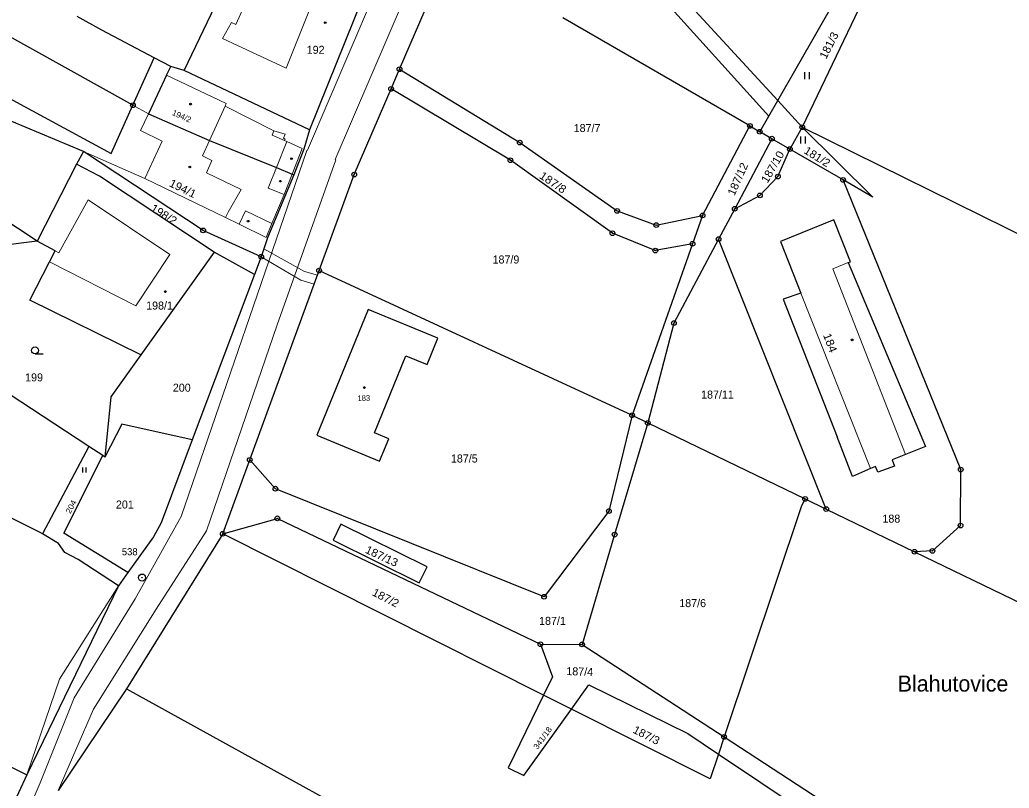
# Model space of a CAD drawing. Extents: x -504006 to -501322, y -1128098 to -1124665.
# Drawn here: x -502549.5 to -502339.3, y -1126824.4 to -1126661.3 of the extents above; entities that cross this region are included whole.
import ezdxf
from ezdxf.enums import TextEntityAlignment as Align

# ---------------------------------------------------------------- set-up
doc = ezdxf.new("R2010")
doc.units = 0
doc.header["$LTSCALE"] = 0.68
for name, color, linetype, lineweight in [('1', 7, 'Continuous', 25), ('13', 7, 'Continuous', 13), ('3', 7, 'Continuous', 25), ('4', 7, 'Continuous', 13), ('5', 7, 'Continuous', 25), ('7', 7, 'Continuous', 13), ('8', 7, 'Continuous', 25)]:
    doc.layers.add(name, color=color, linetype=linetype, lineweight=lineweight)
doc.layers.add('2', color=7, linetype='Continuous')

msp = doc.modelspace()

# ---------------------------------------------------------------- linework, layer by layer
at = {"layer": '1'}
for p, q in [((-502514.61, -1126672.05), (-502498.34, -1126637.96)), ((-502388.53, -1126678.42), (-502367.75, -1126642.18)), ((-502468.87, -1126671.79), (-502458.21, -1126646.98)), ((-502473.55, -1126648.9), (-502487.98, -1126684.63)), ((-502532.13, -1126663.52), (-502537.38, -1126660.61)), ((-502525.52, -1126679.45), (-502556.87, -1126662.01)), ((-502394.44, -1126683.84), (-502434.16, -1126660.88)), ((-502520.99, -1126669.37), (-502532.13, -1126663.52)), ((-502525.52, -1126679.45), (-502520.99, -1126669.37)), ((-502517.46, -1126671.21), (-502520.99, -1126669.37)), ((-502518.34, -1126673.06), (-502522.22, -1126681.29)), ((-502518.34, -1126673.06), (-502517.46, -1126671.21)), ((-502514.61, -1126672.05), (-502517.46, -1126671.21)), ((-502487.98, -1126684.63), (-502514.61, -1126672.05)), ((-502470.66, -1126675.96), (-502468.87, -1126671.79)), ((-502468.87, -1126671.79), (-502443.33, -1126687.38)), ((-502535.97, -1126689.29), (-502570.56, -1126674.86)), ((-502552.7, -1126677.43), (-502530.11, -1126689.67)), ((-502445.31, -1126691.13), (-502470.66, -1126675.96)), ((-502530.11, -1126689.67), (-502525.52, -1126679.45)), ((-502390.44, -1126681.76), (-502388.53, -1126678.42)), ((-502522.22, -1126681.29), (-502509.26, -1126686.91)), ((-502392.34, -1126685.06), (-502390.44, -1126681.76)), ((-502487.98, -1126684.63), (-502489.17, -1126688.78)), ((-502404.48, -1126702.82), (-502394.44, -1126683.84)), ((-502394.44, -1126683.84), (-502392.34, -1126685.06)), ((-502389.77, -1126686.54), (-502392.34, -1126685.06)), ((-502383.3, -1126684.1), (-502243.09, -1126753.39)), ((-502383.3, -1126684.1), (-502368.31, -1126698.95)), ((-502509.26, -1126686.91), (-502495.03, -1126692.69)), ((-502443.33, -1126687.38), (-502422.64, -1126701.87)), ((-502389.77, -1126686.54), (-502397.66, -1126701.4)), ((-502385.94, -1126688.76), (-502389.77, -1126686.54)), ((-502535.97, -1126689.29), (-502537.47, -1126691.97)), ((-502510.58, -1126706), (-502535.97, -1126689.29)), ((-502489.17, -1126688.78), (-502491.34, -1126694.18)), ((-502374.62, -1126695.3), (-502385.94, -1126688.76)), ((-502537.47, -1126691.97), (-502545.88, -1126708.26)), ((-502532.6, -1126694.5), (-502537.47, -1126691.97)), ((-502423.63, -1126706.61), (-502445.31, -1126691.13)), ((-502491.34, -1126694.18), (-502496.89, -1126707.57)), ((-502495.03, -1126692.69), (-502491.67, -1126694.05)), ((-502491.67, -1126694.05), (-502491.34, -1126694.18)), ((-502545.88, -1126708.26), (-502566.86, -1126694.62)), ((-502508.21, -1126710.63), (-502532.6, -1126694.5)), ((-502368.31, -1126698.95), (-502374.62, -1126695.3)), ((-502349.64, -1126756.78), (-502374.62, -1126695.3)), ((-502397.66, -1126701.4), (-502392.31, -1126698.58)), ((-502422.64, -1126701.87), (-502414.31, -1126704.87)), ((-502397.66, -1126701.4), (-502401.08, -1126707.84)), ((-502414.31, -1126704.87), (-502404.48, -1126702.82)), ((-502404.48, -1126702.82), (-502406.61, -1126708.85)), ((-502376.58, -1126703.79), (-502387.96, -1126708.39)), ((-502373.05, -1126712.67), (-502376.58, -1126703.79)), ((-502498.25, -1126711.6), (-502510.58, -1126706)), ((-502414.52, -1126710.3), (-502423.63, -1126706.61)), ((-502545.88, -1126708.26), (-502584.04, -1126713.35)), ((-502542, -1126710.33), (-502545.88, -1126708.26)), ((-502496.89, -1126707.57), (-502498.25, -1126711.6)), ((-502406.61, -1126708.85), (-502419.46, -1126745.24)), ((-502406.61, -1126708.85), (-502414.52, -1126710.3)), ((-502401.08, -1126707.84), (-502410.56, -1126725.68)), ((-502378.21, -1126765.17), (-502401.08, -1126707.84)), ((-502387.96, -1126708.39), (-502383.61, -1126719.33)), ((-502543.2, -1126712.66), (-502542, -1126710.33)), ((-502508.21, -1126710.63), (-502523.8, -1126732.39)), ((-502499.66, -1126715.34), (-502508.21, -1126710.63)), ((-502547.39, -1126720.79), (-502543.2, -1126712.66)), ((-502498.25, -1126711.6), (-502499.66, -1126715.34)), ((-502373.53, -1126712.85), (-502373.05, -1126712.67)), ((-502373.53, -1126712.85), (-502357.15, -1126751.91)), ((-502534.85, -1126751.89), (-502591.17, -1126714.91)), ((-502500.68, -1126754.74), (-502485.95, -1126714.53)), ((-502485.95, -1126714.53), (-502419.46, -1126745.24)), ((-502499.66, -1126715.34), (-502512.9, -1126750.49)), ((-502383.61, -1126719.33), (-502387.33, -1126720.64)), ((-502523.8, -1126732.39), (-502547.39, -1126720.79)), ((-502387.33, -1126720.64), (-502375.92, -1126749.84)), ((-502475.56, -1126722.78), (-502486.4, -1126749.48)), ((-502460.7, -1126728.86), (-502475.56, -1126722.78)), ((-502410.56, -1126725.68), (-502416.13, -1126746.87)), ((-502463.01, -1126734.5), (-502460.7, -1126728.86)), ((-502523.8, -1126732.39), (-502530.23, -1126741.35)), ((-502474.21, -1126749.01), (-502467.52, -1126732.66)), ((-502467.52, -1126732.66), (-502463.01, -1126734.5)), ((-502530.23, -1126741.35), (-502531.47, -1126754.11)), ((-502419.46, -1126745.24), (-502424.37, -1126765.58)), ((-502419.46, -1126745.24), (-502416.13, -1126746.87)), ((-502527.85, -1126747.13), (-502531.47, -1126754.11)), ((-502512.9, -1126750.49), (-502527.85, -1126747.13)), ((-502416.13, -1126746.87), (-502423.16, -1126770.59)), ((-502416.13, -1126746.87), (-502382.7, -1126763)), ((-502512.9, -1126750.49), (-502519.53, -1126768.1)), ((-502486.4, -1126749.48), (-502473.12, -1126755.02)), ((-502471.16, -1126750.26), (-502474.21, -1126749.01)), ((-502473.12, -1126755.02), (-502471.16, -1126750.26)), ((-502372.64, -1126758.22), (-502375.92, -1126749.84)), ((-502534.85, -1126751.89), (-502544.71, -1126770.39)), ((-502531.93, -1126753.81), (-502534.85, -1126751.89)), ((-502357.15, -1126751.91), (-502361.39, -1126753.6)), ((-502540.17, -1126770.24), (-502531.93, -1126753.81)), ((-502531.47, -1126754.11), (-502531.93, -1126753.81)), ((-502506.41, -1126770.39), (-502500.68, -1126754.74)), ((-502495.24, -1126760.83), (-502500.68, -1126754.74)), ((-502361.39, -1126753.6), (-502364.23, -1126754.73)), ((-502364.23, -1126754.73), (-502363.71, -1126756.02)), ((-502368.83, -1126756.55), (-502372.64, -1126758.22)), ((-502367.74, -1126756.12), (-502368.83, -1126756.55)), ((-502367.27, -1126757.31), (-502367.74, -1126756.12)), ((-502363.71, -1126756.02), (-502367.27, -1126757.31)), ((-502349.67, -1126768.66), (-502349.64, -1126756.78)), ((-502438.14, -1126783.76), (-502495.24, -1126760.83)), ((-502545.19, -1126770.1), (-502560.46, -1126762.54)), ((-502382.7, -1126763), (-502383.45, -1126764.45)), ((-502382.7, -1126763), (-502378.21, -1126765.17)), ((-502424.37, -1126765.58), (-502438.14, -1126783.76)), ((-502383.45, -1126764.45), (-502399.9, -1126813.53)), ((-502378.21, -1126765.17), (-502359.46, -1126774.22)), ((-502519.53, -1126768.1), (-502521.15, -1126771.02)), ((-502349.67, -1126768.66), (-502355.65, -1126774.03)), ((-502544.71, -1126770.39), (-502545.19, -1126770.1)), ((-502541.29, -1126772.48), (-502544.71, -1126770.39)), ((-502526.56, -1126778.62), (-502540.17, -1126770.24)), ((-502506.41, -1126770.39), (-502526.88, -1126803.35)), ((-502521.15, -1126771.02), (-502526.56, -1126778.62)), ((-502438.25, -1126804.65), (-502506.41, -1126770.39)), ((-502423.16, -1126770.59), (-502430.09, -1126793.88)), ((-502539.95, -1126774.41), (-502541.29, -1126772.48)), ((-502355.65, -1126774.03), (-502359.46, -1126774.22)), ((-502537.13, -1126775.85), (-502539.95, -1126774.41)), ((-502528.59, -1126781.47), (-502537.13, -1126775.85)), ((-502359.46, -1126774.22), (-502305.89, -1126800.07)), ((-502526.56, -1126778.62), (-502528.59, -1126781.47)), ((-502528.59, -1126781.47), (-502548.07, -1126821.6)), ((-502438.93, -1126793.84), (-502436.36, -1126800.79)), ((-502438.93, -1126793.84), (-502430.09, -1126793.88)), ((-502430.09, -1126793.88), (-502399.9, -1126813.53)), ((-502436.36, -1126800.79), (-502438.25, -1126804.65)), ((-502526.88, -1126803.35), (-502541.38, -1126824.92)), ((-502526.88, -1126803.35), (-502474.26, -1126832.3)), ((-502432.33, -1126807.62), (-502428.63, -1126802.48)), ((-502428.63, -1126802.48), (-502407.61, -1126812.8)), ((-502582.38, -1126804.36), (-502548.07, -1126821.6)), ((-502438.25, -1126804.65), (-502445.8, -1126820.05)), ((-502432.33, -1126807.62), (-502438.25, -1126804.65)), ((-502442.47, -1126821.73), (-502432.33, -1126807.62)), ((-502402.88, -1126822.43), (-502432.33, -1126807.62)), ((-502407.61, -1126812.8), (-502401.11, -1126817.15)), ((-502399.9, -1126813.53), (-502401.11, -1126817.15)), ((-502399.9, -1126813.53), (-502375.12, -1126829.65)), ((-502401.11, -1126817.15), (-502402.88, -1126822.43)), ((-502401.11, -1126817.15), (-502377.47, -1126832.95)), ((-502445.8, -1126820.05), (-502442.47, -1126821.73)), ((-502548.07, -1126821.6), (-502553.7, -1126833.67))]:
    msp.add_line(p, q, dxfattribs=at)
for points in [[(-502364.16, -1126643.95), (-502383.3, -1126684.1), (-502385.94, -1126688.76)], [(-502485.95, -1126714.53), (-502478.49, -1126694.17), (-502470.66, -1126675.96)], [(-502392.31, -1126698.58), (-502388.49, -1126694.59), (-502385.94, -1126688.76)], [(-502506.41, -1126770.39), (-502494.82, -1126767.13), (-502438.93, -1126793.84)]]:
    msp.add_lwpolyline(points, dxfattribs=at)
msp.add_lwpolyline([(-502481.3, -1126768.38), (-502482.93, -1126771.78), (-502464.69, -1126780.81), (-502463.01, -1126777.41)], close=True, dxfattribs=at)
at = {"layer": '13'}
for points in [[(-502522.22, -1126681.29), (-502518.34, -1126673.06), (-502517.46, -1126671.21), (-502520.99, -1126669.37), (-502525.52, -1126679.45)], [(-502486.31, -1126715.52), (-502489.02, -1126714.7), (-502497.68, -1126709.92), (-502498.25, -1126711.6), (-502489.8, -1126716.56), (-502487, -1126717.4)]]:
    msp.add_lwpolyline(points, close=True, dxfattribs=at)
at = {"layer": '3'}
for p, q in [((-502382.791, -1126673.9), (-502382.791, -1126672.4)), ((-502381.79, -1126673.9), (-502381.79, -1126672.4)), ((-502383.611, -1126687.59), (-502383.611, -1126686.09)), ((-502382.61, -1126687.59), (-502382.61, -1126686.09)), ((-502546.303, -1126732.23), (-502544.553, -1126732.23)), ((-502536.148, -1126757.42), (-502536.148, -1126756.37)), ((-502535.447, -1126757.42), (-502535.447, -1126756.37))]:
    msp.add_line(p, q, dxfattribs=at)
msp.add_circle((-502546.3029, -1126731.4798), 0.75, dxfattribs=at)
at = {"layer": '4'}
for p, q in [((-502468.35, -1126642), (-502488.41, -1126689.01)), ((-502503.66, -1126662.3), (-502495.74, -1126644.98)), ((-502462.54, -1126644.48), (-502482.56, -1126690.99)), ((-502418.68, -1126645.66), (-502388.53, -1126678.42)), ((-502484.35, -1126649.98), (-502492.98, -1126671.58)), ((-502420.74, -1126648.16), (-502390.44, -1126681.76)), ((-502506.48, -1126665.27), (-502504.55, -1126661.89)), ((-502504.55, -1126661.89), (-502503.66, -1126662.3)), ((-502492.98, -1126671.58), (-502506.48, -1126665.27)), ((-502518.34, -1126673.06), (-502505.67, -1126679.1)), ((-502505.67, -1126679.1), (-502505.92, -1126679.64)), ((-502388.53, -1126678.42), (-502383.3, -1126684.1)), ((-502523.89, -1126684.83), (-502522.22, -1126681.29)), ((-502505.92, -1126679.64), (-502509.26, -1126686.91)), ((-502505.92, -1126679.64), (-502495.56, -1126684.88)), ((-502519.28, -1126687.05), (-502523.89, -1126684.83)), ((-502495.56, -1126684.88), (-502495.94, -1126685.81)), ((-502495.94, -1126685.81), (-502493.27, -1126686.93)), ((-502493.13, -1126685.55), (-502495.56, -1126684.88)), ((-502493.5, -1126686.43), (-502493.13, -1126685.55)), ((-502523, -1126694.96), (-502519.28, -1126687.05)), ((-502509.26, -1126686.91), (-502510.74, -1126690.15)), ((-502495.03, -1126692.69), (-502492.81, -1126687.11)), ((-502493.16, -1126686.65), (-502493.5, -1126686.43)), ((-502493.27, -1126686.93), (-502493.16, -1126686.65)), ((-502492.81, -1126687.11), (-502493.27, -1126686.93)), ((-502492.81, -1126687.11), (-502489.54, -1126688.62)), ((-502535.97, -1126689.29), (-502523, -1126694.96)), ((-502488.54, -1126689.02), (-502515.26, -1126766.72)), ((-502489.54, -1126688.62), (-502491.67, -1126694.05)), ((-502488.41, -1126689.01), (-502488.54, -1126689.02)), ((-502510.74, -1126690.15), (-502508.74, -1126691.14)), ((-502508.74, -1126691.14), (-502509.84, -1126693.77)), ((-502482.4, -1126691.01), (-502494.88, -1126726.05)), ((-502482.56, -1126690.99), (-502482.4, -1126691.01)), ((-502509.84, -1126693.77), (-502502.5, -1126697.31)), ((-502496.77, -1126697.07), (-502495.03, -1126692.69)), ((-502491.67, -1126694.05), (-502493.38, -1126698.42)), ((-502505.86, -1126703.24), (-502523, -1126694.96)), ((-502502.5, -1126697.31), (-502505.24, -1126702.15)), ((-502493.38, -1126698.42), (-502496.77, -1126697.07)), ((-502493.38, -1126698.42), (-502495.99, -1126704.56)), ((-502535.04, -1126699.54), (-502541.24, -1126710.74)), ((-502517.69, -1126711.15), (-502535.04, -1126699.54)), ((-502505.24, -1126702.15), (-502505.86, -1126703.24)), ((-502502.93, -1126704.65), (-502501.58, -1126701.85)), ((-502501.58, -1126701.85), (-502495.99, -1126704.56)), ((-502505.86, -1126703.24), (-502502.93, -1126704.65)), ((-502497.2, -1126707.48), (-502502.93, -1126704.65)), ((-502495.99, -1126704.56), (-502497.2, -1126707.48)), ((-502541.24, -1126710.74), (-502542, -1126710.33)), ((-502543.2, -1126712.66), (-502524.87, -1126722.02)), ((-502524.87, -1126722.02), (-502517.69, -1126711.15)), ((-502373.53, -1126712.85), (-502376.8, -1126714.15)), ((-502376.8, -1126714.15), (-502361.39, -1126753.6)), ((-502368.83, -1126756.55), (-502383.61, -1126719.33)), ((-502494.88, -1126726.05), (-502509.86, -1126769.79)), ((-502515.26, -1126766.72), (-502525, -1126784.2)), ((-502509.86, -1126769.79), (-502520.6, -1126786.4)), ((-502528.59, -1126781.47), (-502541.12, -1126801.29)), ((-502525, -1126784.2), (-502538, -1126805.2)), ((-502520.6, -1126786.4), (-502533.9, -1126807.6)), ((-502541.12, -1126801.29), (-502548.07, -1126821.6)), ((-502538, -1126805.2), (-502545.2, -1126823.24)), ((-502533.9, -1126807.6), (-502541.38, -1126824.92)), ((-502549.15, -1126832.4), (-502545.2, -1126823.24))]:
    msp.add_line(p, q, dxfattribs=at)
at = {"layer": '5'}
for centre in [(-502484.6468, -1126661.9092), (-502513.2668, -1126679.1992), (-502491.8068, -1126690.7992), (-502513.4268, -1126692.5492), (-502494.1768, -1126695.5592), (-502501.0268, -1126704.0492), (-502518.6068, -1126718.9892), (-502372.7168, -1126729.2492), (-502476.3368, -1126739.3592)]:
    msp.add_circle(centre, 0.175, dxfattribs=at)
at = {"layer": '8'}
for centre, radius in [((-502468.87, -1126671.7899), 0.5), ((-502468.87, -1126671.7899), 0.0303), ((-502470.66, -1126675.9599), 0.5), ((-502470.66, -1126675.9599), 0.0303), ((-502525.52, -1126679.4499), 0.5), ((-502525.52, -1126679.4499), 0.0303), ((-502394.44, -1126683.8399), 0.5), ((-502383.3, -1126684.0999), 0.5), ((-502394.44, -1126683.8399), 0.0303), ((-502392.34, -1126685.0599), 0.5), ((-502392.34, -1126685.0599), 0.0303), ((-502383.3, -1126684.0999), 0.0303), ((-502443.33, -1126687.3799), 0.5), ((-502443.33, -1126687.3799), 0.0303), ((-502389.77, -1126686.5399), 0.5), ((-502389.77, -1126686.5399), 0.0303), ((-502385.94, -1126688.7599), 0.5), ((-502385.94, -1126688.7599), 0.0303), ((-502445.31, -1126691.1299), 0.5), ((-502445.31, -1126691.1299), 0.0303), ((-502478.49, -1126694.1699), 0.5), ((-502478.49, -1126694.1699), 0.0303), ((-502388.49, -1126694.5899), 0.5), ((-502388.49, -1126694.5899), 0.0303), ((-502374.62, -1126695.2999), 0.5), ((-502374.62, -1126695.2999), 0.0303), ((-502392.31, -1126698.5799), 0.5), ((-502392.31, -1126698.5799), 0.0303), ((-502422.64, -1126701.8699), 0.5), ((-502422.64, -1126701.8699), 0.0303), ((-502404.48, -1126702.8199), 0.5), ((-502397.66, -1126701.3999), 0.5), ((-502397.66, -1126701.3999), 0.0303), ((-502414.31, -1126704.8699), 0.5), ((-502404.48, -1126702.8199), 0.0303), ((-502510.58, -1126705.9999), 0.5), ((-502510.58, -1126705.9999), 0.0303), ((-502423.63, -1126706.6099), 0.5), ((-502423.63, -1126706.6099), 0.0303), ((-502414.31, -1126704.8699), 0.0303), ((-502406.61, -1126708.8499), 0.5), ((-502406.61, -1126708.8499), 0.0303), ((-502401.08, -1126707.8399), 0.5), ((-502401.08, -1126707.8399), 0.0303), ((-502498.25, -1126711.5999), 0.5), ((-502414.52, -1126710.2999), 0.5), ((-502414.52, -1126710.2999), 0.0303), ((-502498.25, -1126711.5999), 0.0303), ((-502485.95, -1126714.5299), 0.5), ((-502485.95, -1126714.5299), 0.0303), ((-502410.56, -1126725.6799), 0.5), ((-502410.56, -1126725.6799), 0.0303), ((-502419.46, -1126745.2399), 0.5), ((-502419.46, -1126745.2399), 0.0303), ((-502416.13, -1126746.8699), 0.5), ((-502416.13, -1126746.8699), 0.0303), ((-502500.68, -1126754.7399), 0.5), ((-502500.68, -1126754.7399), 0.0303), ((-502349.64, -1126756.7799), 0.5), ((-502349.64, -1126756.7799), 0.0303), ((-502495.24, -1126760.8299), 0.5), ((-502495.24, -1126760.8299), 0.0303), ((-502382.7, -1126762.9999), 0.5), ((-502382.7, -1126762.9999), 0.0303), ((-502424.37, -1126765.5799), 0.5), ((-502424.37, -1126765.5799), 0.0303), ((-502378.21, -1126765.1699), 0.5), ((-502378.21, -1126765.1699), 0.0303), ((-502494.82, -1126767.1299), 0.5), ((-502494.82, -1126767.1299), 0.0303), ((-502506.41, -1126770.3899), 0.5), ((-502349.67, -1126768.6599), 0.5), ((-502349.67, -1126768.6599), 0.0303), ((-502506.41, -1126770.3899), 0.0303), ((-502423.16, -1126770.5899), 0.5), ((-502423.16, -1126770.5899), 0.0303), ((-502359.46, -1126774.2199), 0.5), ((-502355.65, -1126774.0299), 0.5), ((-502355.65, -1126774.0299), 0.0303), ((-502359.46, -1126774.2199), 0.0303), ((-502523.56, -1126779.6998), 0.75), ((-502523.56, -1126779.6998), 0.03), ((-502438.14, -1126783.7599), 0.5), ((-502438.14, -1126783.7599), 0.0303), ((-502438.93, -1126793.8399), 0.5), ((-502438.93, -1126793.8399), 0.0303), ((-502430.09, -1126793.8799), 0.5), ((-502430.09, -1126793.8799), 0.0303), ((-502399.9, -1126813.5299), 0.5), ((-502399.9, -1126813.5299), 0.0303)]:
    msp.add_circle(centre, radius, dxfattribs=at)

# ---------------------------------------------------------------- texts
at = {"layer": '2'}
for s, height, rotation, width, p in [('181/3', 1.7, 63, 1.05, (-502376.8803, -1126667.1154)), ('194/2', 1.2, 336, 1.05, (-502515.377, -1126682.3085)), ('181/2', 1.7, 328, 1.05, (-502380.5859, -1126691.0929)), ('187/12', 1.7, 66, 1.05, (-502396.2327, -1126695.4562)), ('194/1', 1.7, 334, 1.05, (-502515.2666, -1126697.8736)), ('198/2', 1.7, 328, 1.05, (-502519.3759, -1126703.3229)), ('184', 1.7, 291, 1.1, (-502378.1668, -1126730.1664)), ('204', 1.2, 63, 1.1, (-502538.1216, -1126764.9374)), ('187/13', 1.7, 335, 1.05, (-502472.9967, -1126775.9201)), ('187/2', 1.7, 333, 1.05, (-502472.1854, -1126784.7587)), ('341/18', 1.2, 54, 1.1, (-502437.9862, -1126814.1157)), ('187/3', 1.7, 333, 1.05, (-502416.7954, -1126813.9087))]:
    msp.add_text(s, height=height, rotation=rotation, dxfattribs=dict(at, width=width)).set_placement(p, align=Align.CENTER)
for s, p in [('192', (-502486.689, -1126668.525)), ('198/1', (-502519.85, -1126722.805)), ('199', (-502546.509, -1126738.055)), ('200', (-502515.129, -1126740.245)), ('201', (-502527.219, -1126765.045)), ('188', (-502364.379, -1126768.035))]:
    msp.add_text(s, height=1.7, dxfattribs=at).set_placement(p, align=Align.CENTER)
for s, p in [('187/7', (-502431.87, -1126685.135)), ('187/9', (-502449.1, -1126713.035)), ('187/11', (-502404.8, -1126741.705)), ('187/5', (-502457.95, -1126755.275)), ('187/6', (-502409.44, -1126785.975)), ('187/1', (-502439.22, -1126789.735))]:
    msp.add_text(s, height=1.7, dxfattribs=at).set_placement(p)
for s, rotation, width, p in [('187/10', 60, 1.05, (-502390.691, -1126696.112)), ('187/8', 326, 1.1, (-502439.337, -1126694.782))]:
    msp.add_text(s, height=1.7, rotation=rotation, dxfattribs=dict(at, width=width)).set_placement(p)
for s, height, rotation, p in [('183', 1.2, 2, (-502476.4284, -1126742.209)), ('187/4', 1.7, 358, (-502430.6097, -1126800.4845))]:
    msp.add_text(s, height=height, rotation=rotation, dxfattribs=at).set_placement(p, align=Align.CENTER)
at = {"layer": '7'}
msp.add_text('Blahutovice', height=3.4, dxfattribs=at).set_placement((-502351.27, -1126803.9), align=Align.CENTER)
at = {"layer": '8'}
msp.add_text('538', height=1.5, dxfattribs=at).set_placement((-502524.509, -1126774.965), align=Align.RIGHT)

doc.saveas('drawing.dxf')
